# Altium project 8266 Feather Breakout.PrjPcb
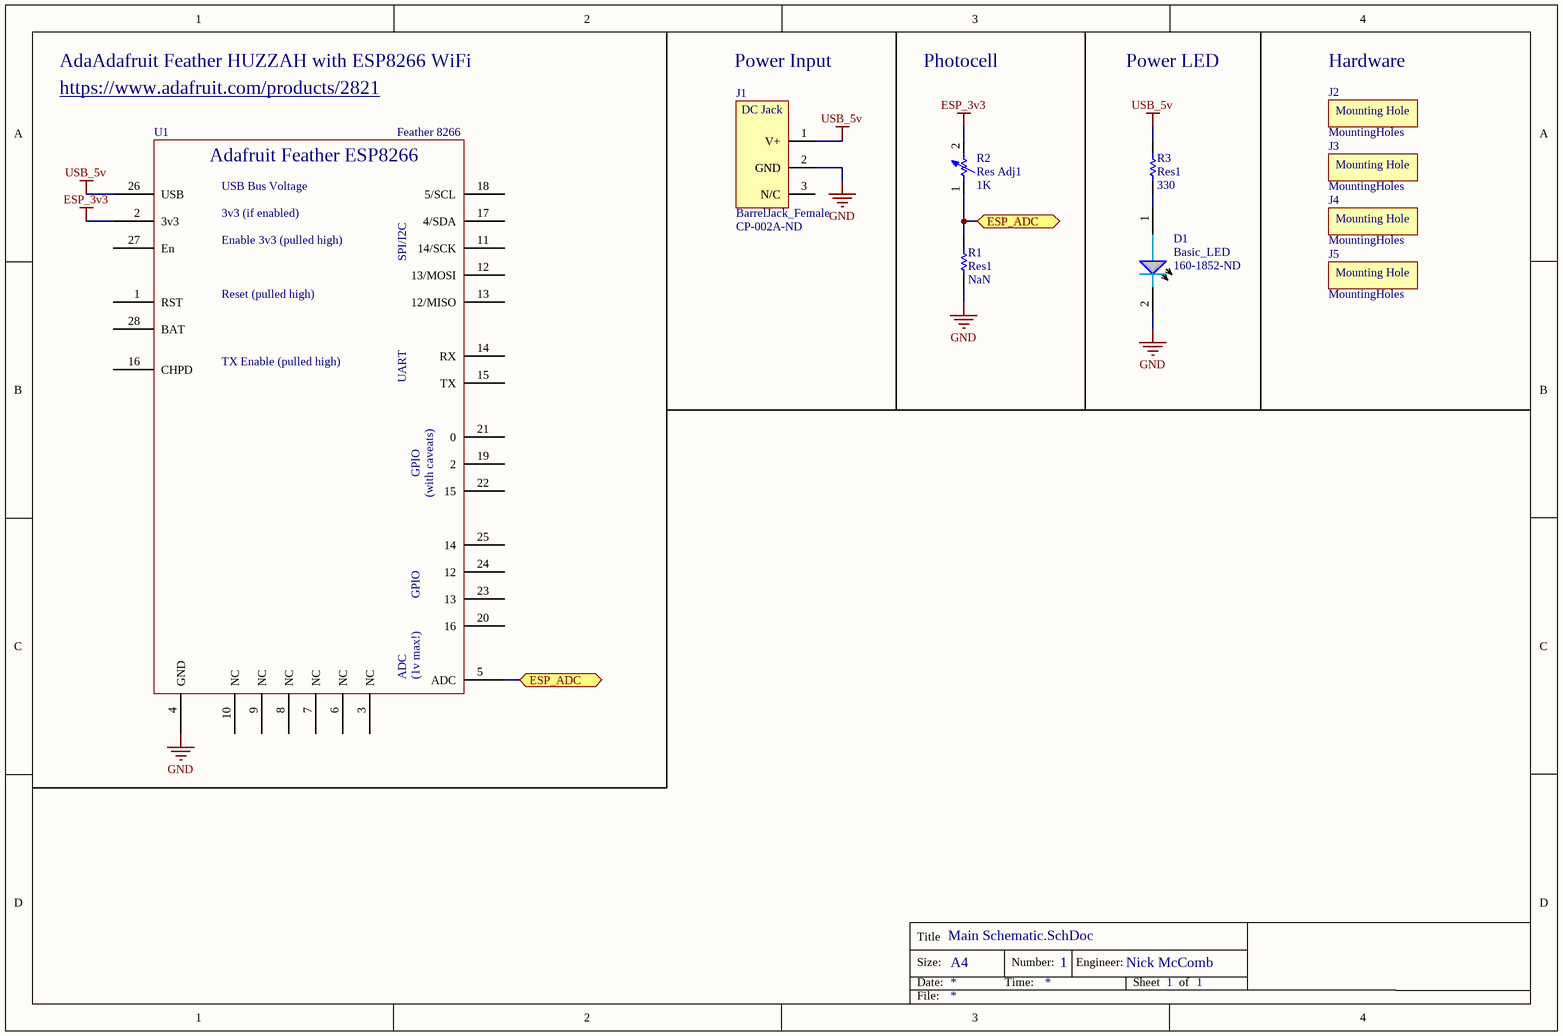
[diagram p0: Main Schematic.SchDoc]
ProjectEngineer: Nick McComb
1 sheet, 10 parts. Net scope: flat (ports and power ports of the same name join across sheets).
Board file: Feather Breakout.PcbDoc

## Sheet Main Schematic.SchDoc
size A4; CompanyName: Ocean Mixing Group; DrawnBy: Nick McComb; DocumentNumber: 1; SheetNumber: 1; SheetTotal: 1

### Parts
D1  Basic_LED  Supplier Part Number 1: 160-1852-ND  [Basic_LED - Through hole]
J1  BarrelJack_Female  Supplier Part Number 1: CP-002A-ND  [BarrelJack]
J2  MountingHoles  [Mounting Hole - Single]
J3  MountingHoles  [Mounting Hole - Single]
J4  MountingHoles  [Mounting Hole - Single]
J5  MountingHoles  [Mounting Hole - Single]
R1  Res1  Resistance (Ohms): NaN  [AXIAL-0.3]
R2  Res Adj1  value 1K  [Photocell]
R3  Res1  Resistance (Ohms): 330  [AXIAL-0.3]
U1  Feather 8266  [Adafruit Feather 8266]

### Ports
ESP_ADC

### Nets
ESP_3v3: R2.2 U1.2(3v3)
GND: D1.2 J1.2(GND) R1.1 U1.4(GND)
USB_5v: J1.1(V+) R3.1 U1.26(USB)
NetD1_1: D1.1 R3.2
NetR1_2: R1.2 R2.1 U1.5(ADC) ; port ESP_ADC

Not connected (* = marked no-connect by the designer): J1 3(N/C); U1 1(RST) 3(NC) 6(NC) 7(NC) 8(NC) 9(NC) 10(NC) 11(14/SCK) 12(13/MOSI) 13(12/MISO) 14(RX) 15(TX) 16(CHPD) 17(4/SDA) 18(5/SCL) 19(2) 20(16) 21(0) 22(15) 23(13) 24(12) 25(14) 27(En) 28(BAT)

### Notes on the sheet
- AdaAdafruit Feather HUZZAH with ESP8266 WiFi
- https://www.adafruit.com/products/2821
- Power Input
- Photocell
- Power LED
- (near J2) Hardware
- Title
- Size:
- Date:
- A4
- Time:
- Number:
- Engineer:
- Sheet
- of
- File:

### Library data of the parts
D1 = Basic_LED: Manufacturer: Lite-On Inc.; Manufacturer Part Number: LTL2R3KGD-EM; Color: Green; Lens Transparency: Diffused; Millicandela Rating: 38mcd; Lens Style/Size: Round with Domed Top, 5.00mm; Voltage - Forward (Vf) (Typ): 1.8V; Current - Test: 2mA; Viewing Angle: 30°; Wavelength - Dominant: 570nm; Wavelength - Peak: 568nm
J1 = BarrelJack_Female: Manufacturer: CUI Inc; Manufacturer Part Number: PJ-002A; Connector Type: Jack; Gender: Male; Plug/Mating Plug Diameter: 2.1mm ID, 5.5mm OD; Number of Positions/Contacts: 2 Conductors, 3 Contacts; Internal Switch(s): Single Switch, Normally Closed; Shielding: Unshielded; Voltage - Rated: 16VDC; Current Rating: 2.5A
R1 = Res1: Resistor; Value: 1K
R2 = Res Adj1: Variable Resistor
R3 = Res1: Resistor; Value: 330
